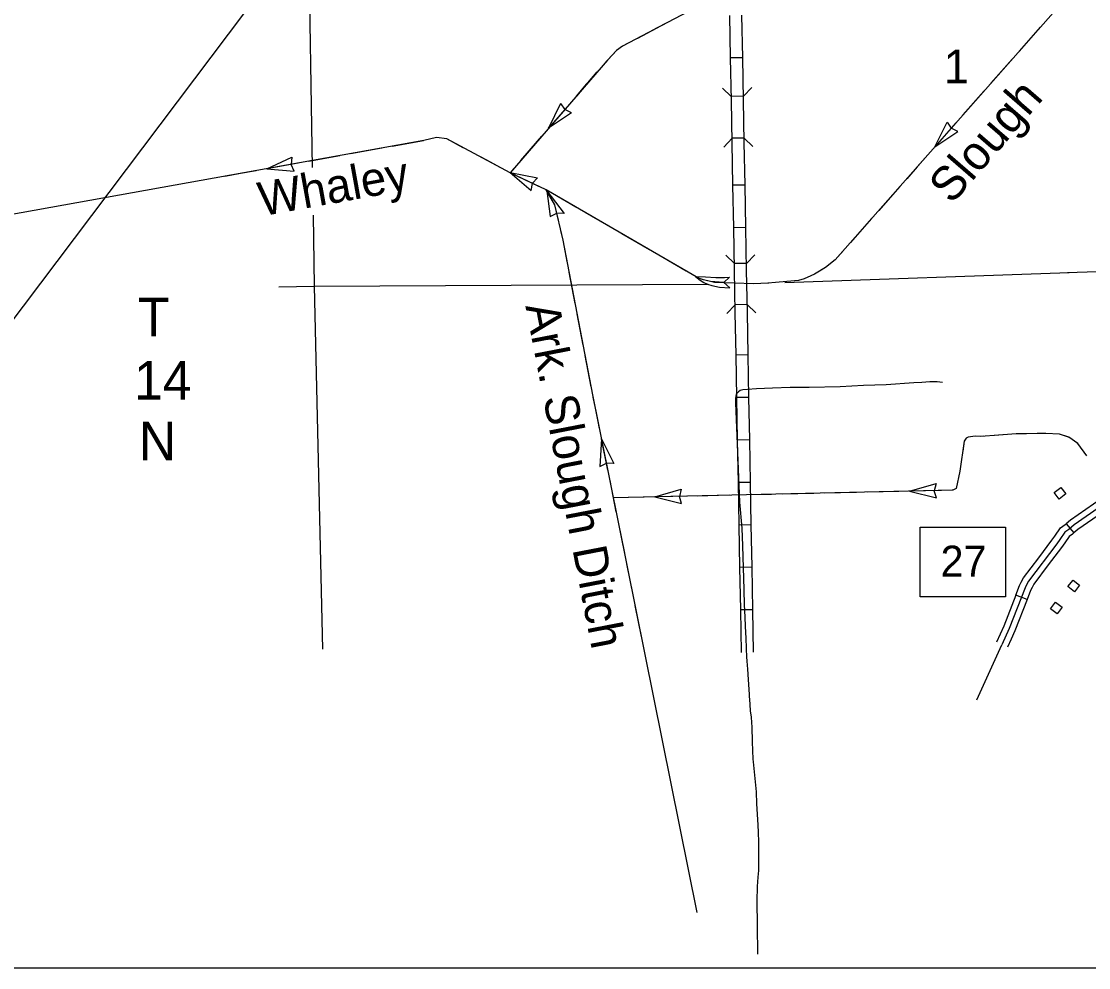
# Model space of a CAD drawing. Extents: x 1671357 to 13005564, y 567358 to 14261451.
# Drawn here: x 12758292.019 to 12758296.447, y 14259938.354 to 14259942.281 of the extents above; entities that cross this region are included whole.
import ezdxf

# ---------------------------------------------------------------- set-up
doc = ezdxf.new("R2010")
doc.units = 0
for name, color, linetype in [('31', 7, 'Continuous'), ('32', 7, 'Continuous'), ('35', 7, 'Continuous'), ('38', 7, 'Continuous'), ('43', 7, 'Continuous'), ('5', 7, 'Continuous'), ('56', 7, 'Continuous'), ('Default', 7, 'Continuous')]:
    doc.layers.add(name, color=color, linetype=linetype)

msp = doc.modelspace()

# ---------------------------------------------------------------- linework, layer by layer
at = {"layer": '31'}
for p, q in [((12758296.3532, 14259940.196), (12758296.3854, 14259940.1577)), ((12758296.2798, 14259940.025), (12758296.2798, 14259940.025)), ((12758296.1917, 14259939.8817), (12758296.1451, 14259939.9))]:
    msp.add_line(p, q, dxfattribs=at)
for points in [[(12758296.6997, 14259940.4082), (12758296.387, 14259940.1916), (12758296.3643, 14259940.1726), (12758296.3484, 14259940.1613), (12758296.3272, 14259940.1307), (12758296.3148, 14259940.1128), (12758296.1978, 14259939.9581), (12758296.1897, 14259939.9424), (12758296.1835, 14259939.9294), (12758296.1177, 14259939.7617), (12758296.0875, 14259939.6941)], [(12758296.4987, 14259940.2995), (12758296.3718, 14259940.2116), (12758296.3532, 14259940.196)], [(12758296.5272, 14259940.2583), (12758296.4022, 14259940.1717), (12758296.3854, 14259940.1577)], [(12758296.2398, 14259940.0552), (12758296.2945, 14259940.1274), (12758296.3066, 14259940.1449), (12758296.3303, 14259940.1792), (12758296.349, 14259940.1925), (12758296.3532, 14259940.196)], [(12758296.3854, 14259940.1577), (12758296.3796, 14259940.1528), (12758296.3665, 14259940.1434), (12758296.3478, 14259940.1164), (12758296.3351, 14259940.0981), (12758296.2798, 14259940.025)], [(12758296.1451, 14259939.9), (12758296.1605, 14259939.9394), (12758296.1672, 14259939.9535), (12758296.1765, 14259939.9715), (12758296.2398, 14259940.0552)], [(12758296.2798, 14259940.025), (12758296.219, 14259939.9447), (12758296.2121, 14259939.9313), (12758296.2065, 14259939.9194), (12758296.1917, 14259939.8817)], [(12758296.1451, 14259939.9), (12758296.0946, 14259939.7713), (12758296.0795, 14259939.7376)], [(12758296.1917, 14259939.8817), (12758296.1408, 14259939.752), (12758296.1253, 14259939.7172)], [(12758296.0795, 14259939.7376), (12758296.0647, 14259939.7044)], [(12758295.9837, 14259939.4646), (12758296.0875, 14259939.6941)], [(12758296.1253, 14259939.7172), (12758296.1104, 14259939.6839)]]:
    msp.add_lwpolyline(points, dxfattribs=at)
at = {"layer": '32'}
for p, q in [((12758295.0118, 14259942.1303), (12758294.9618, 14259942.1294)), ((12758295.0148, 14259941.9702), (12758294.9647, 14259941.9692)), ((12758295.018, 14259941.7967), (12758294.9679, 14259941.7958)), ((12758295.0215, 14259941.6016), (12758294.9715, 14259941.6007)), ((12758295.0248, 14259941.4253), (12758294.9747, 14259941.4244)), ((12758295.0275, 14259941.2767), (12758294.9774, 14259941.2758)), ((12758295.0306, 14259941.1059), (12758294.9806, 14259941.105)), ((12758295.0345, 14259940.8966), (12758294.9844, 14259940.8957)), ((12758295.0377, 14259940.7203), (12758294.9877, 14259940.7194)), ((12758295.041, 14259940.5441), (12758294.9909, 14259940.5432)), ((12758295.0442, 14259940.3678), (12758294.9942, 14259940.3669)), ((12758295.0475, 14259940.1916), (12758294.9974, 14259940.1907)), ((12758295.0507, 14259940.0153), (12758295.0006, 14259940.0144)), ((12758295.0539, 14259939.8391), (12758295.0039, 14259939.8382))]:
    msp.add_line(p, q, dxfattribs=at)
for points in [[(12758291.3155, 14259940.156), (12758292.9509, 14259942.3231)], [(12758294.9618, 14259942.1294), (12758294.9585, 14259942.3057)], [(12758295.0118, 14259942.1303), (12758295.0086, 14259942.3066)], [(12758294.965, 14259941.9532), (12758294.9618, 14259942.1294)], [(12758295.0151, 14259941.9541), (12758295.0118, 14259942.1303)], [(12758294.9682, 14259941.7769), (12758294.965, 14259941.9532)], [(12758295.0183, 14259941.7778), (12758295.0151, 14259941.9541)], [(12758294.9715, 14259941.6007), (12758294.9682, 14259941.7769)], [(12758295.0215, 14259941.6016), (12758295.0183, 14259941.7778)], [(12758294.9747, 14259941.4244), (12758294.9715, 14259941.6007)], [(12758295.0248, 14259941.4253), (12758295.0215, 14259941.6016)], [(12758294.978, 14259941.2482), (12758294.9747, 14259941.4244)], [(12758295.028, 14259941.2491), (12758295.0248, 14259941.4253)], [(12758294.9812, 14259941.0719), (12758294.978, 14259941.2482)], [(12758295.0313, 14259941.0728), (12758295.028, 14259941.2491)], [(12758294.9844, 14259940.8957), (12758294.9812, 14259941.0719)], [(12758295.0345, 14259940.8966), (12758295.0313, 14259941.0728)], [(12758294.9877, 14259940.7194), (12758294.9844, 14259940.8957)], [(12758295.0377, 14259940.7203), (12758295.0345, 14259940.8966)], [(12758294.9909, 14259940.5432), (12758294.9877, 14259940.7194)], [(12758295.041, 14259940.5441), (12758295.0377, 14259940.7203)], [(12758294.9942, 14259940.3669), (12758294.9909, 14259940.5432)], [(12758295.0442, 14259940.3678), (12758295.041, 14259940.5441)], [(12758294.9974, 14259940.1907), (12758294.9942, 14259940.3669)], [(12758295.0475, 14259940.1916), (12758295.0442, 14259940.3678)], [(12758295.0006, 14259940.0144), (12758294.9974, 14259940.1907)], [(12758295.0507, 14259940.0153), (12758295.0475, 14259940.1916)], [(12758295.0039, 14259939.8382), (12758295.0006, 14259940.0144)], [(12758295.0539, 14259939.8391), (12758295.0507, 14259940.0153)], [(12758295.0071, 14259939.6619), (12758295.0039, 14259939.8382)], [(12758295.0572, 14259939.6629), (12758295.0539, 14259939.8391)]]:
    msp.add_lwpolyline(points, dxfattribs=at)
at = {"layer": '35'}
for p, q in [((12758294.2565, 14259941.9407), (12758294.2737, 14259941.9155)), ((12758294.3014, 14259941.902), (12758294.274, 14259941.9153))]:
    msp.add_line(p, q, dxfattribs=at)
for points in [[(12758294.9447, 14259942.4071), (12758294.5128, 14259942.1776), (12758294.4877, 14259942.1599), (12758294.4502, 14259942.1202), (12758294.0477, 14259941.6529)], [(12758294.0629, 14259941.6705), (12758294.0477, 14259941.6529)]]:
    msp.add_lwpolyline(points, dxfattribs=at)
at = {"layer": '38'}
for p, q in [((12758294.9896, 14259941.9698), (12758294.9896, 14259941.9698)), ((12758294.9928, 14259941.7961), (12758294.9928, 14259941.7961)), ((12758295.0053, 14259941.105), (12758295.0053, 14259941.105))]:
    msp.add_line(p, q, dxfattribs=at)
for points in [[(12758294.9285, 14259942.0041), (12758294.9646, 14259941.9693)], [(12758295.0148, 14259941.9702), (12758295.0495, 14259942.0063)], [(12758294.9679, 14259941.7957), (12758294.9331, 14259941.7597)], [(12758295.0539, 14259941.762), (12758295.0179, 14259941.7967)], [(12758294.9775, 14259941.2758), (12758294.9417, 14259941.3108)], [(12758295.0625, 14259941.3126), (12758295.0275, 14259941.2768)], [(12758294.9807, 14259941.1049), (12758294.9459, 14259941.0688)], [(12758295.0668, 14259941.071), (12758295.0307, 14259941.1058)]]:
    msp.add_lwpolyline(points, dxfattribs=at)
at = {"layer": '43'}
for p, q in [((12758294.2565, 14259941.9407), (12758294.2067, 14259941.8375)), ((12758294.3014, 14259941.902), (12758294.2067, 14259941.8375)), ((12758295.8089, 14259941.7606), (12758295.8598, 14259941.8632)), ((12758295.8598, 14259941.8632), (12758295.8767, 14259941.8378)), ((12758295.8089, 14259941.7606), (12758295.9043, 14259941.824)), ((12758295.9043, 14259941.824), (12758295.877, 14259941.8376)), ((12758293.037, 14259941.669), (12758293.1407, 14259941.7177)), ((12758293.1407, 14259941.7177), (12758293.1381, 14259941.6873)), ((12758293.037, 14259941.669), (12758293.1512, 14259941.6593)), ((12758293.1512, 14259941.6593), (12758293.1382, 14259941.6869)), ((12758294.0471, 14259941.6532), (12758294.1343, 14259941.5788)), ((12758294.0471, 14259941.6532), (12758294.1598, 14259941.6324)), ((12758294.1598, 14259941.6324), (12758294.14, 14259941.6092)), ((12758294.1343, 14259941.5788), (12758294.1398, 14259941.6088)), ((12758294.199, 14259941.578), (12758294.2134, 14259941.4706)), ((12758294.199, 14259941.578), (12758294.2711, 14259941.484)), ((12758294.2134, 14259941.4706), (12758294.2403, 14259941.4849)), ((12758294.2711, 14259941.484), (12758294.2407, 14259941.485)), ((12758294.9566, 14259941.2201), (12758294.9336, 14259941.1972)), ((12758294.9578, 14259941.1748), (12758294.9336, 14259941.1972)), ((12758294.4265, 14259940.5485), (12758294.4193, 14259940.4341)), ((12758294.4265, 14259940.5485), (12758294.4775, 14259940.4458)), ((12758294.4193, 14259940.4341), (12758294.4466, 14259940.4477)), ((12758294.4775, 14259940.4458), (12758294.447, 14259940.4477)), ((12758294.6467, 14259940.3071), (12758294.7566, 14259940.3392)), ((12758294.7566, 14259940.3392), (12758294.7494, 14259940.3096)), ((12758295.7041, 14259940.3308), (12758295.8141, 14259940.363)), ((12758295.8141, 14259940.363), (12758295.8068, 14259940.3333)), ((12758294.6467, 14259940.3071), (12758294.758, 14259940.2799)), ((12758294.758, 14259940.2799), (12758294.7494, 14259940.3092)), ((12758295.7041, 14259940.3308), (12758295.8154, 14259940.3037)), ((12758295.8154, 14259940.3037), (12758295.8068, 14259940.3329))]:
    msp.add_line(p, q, dxfattribs=at)
for points in [[(12758296.435, 14259942.4717), (12758295.3961, 14259941.2916), (12758295.3552, 14259941.2598), (12758295.3095, 14259941.2316), (12758295.2671, 14259941.2128), (12758295.2433, 14259941.2062), (12758295.1162, 14259941.1942), (12758295.0582, 14259941.1913), (12758294.895, 14259941.198), (12758294.8485, 14259941.209), (12758294.8278, 14259941.2155), (12758294.1967, 14259941.582), (12758294.0477, 14259941.6529), (12758293.7846, 14259941.7931), (12758293.7419, 14259941.7995), (12758293.689, 14259941.786), (12758291.7325, 14259941.4348), (12758291.6882, 14259941.4307), (12758291.6611, 14259941.4324), (12758291.6542, 14259941.4341)], [(12758294.6917, 14259942.2727), (12758294.575, 14259942.2107)], [(12758294.6917, 14259942.2727), (12758294.6334, 14259942.2417)], [(12758296.2457, 14259942.2567), (12758296.1584, 14259942.1575)], [(12758294.5944, 14259942.221), (12758294.575, 14259942.2107)], [(12758294.5361, 14259942.19), (12758294.5128, 14259942.1776), (12758294.4877, 14259942.1599), (12758294.4733, 14259942.1439), (12758294.4502, 14259942.1202), (12758294.4368, 14259942.1047)], [(12758294.5361, 14259942.19), (12758294.5128, 14259942.1776), (12758294.4877, 14259942.1599), (12758294.4817, 14259942.1532)], [(12758294.4512, 14259942.1213), (12758294.4502, 14259942.1202), (12758294.4368, 14259942.1047)], [(12758296.1293, 14259942.1244), (12758296.0419, 14259942.0252)], [(12758294.3218, 14259941.9711), (12758294.408, 14259942.0713)], [(12758294.3937, 14259942.0546), (12758294.408, 14259942.0713)], [(12758294.3649, 14259942.0212), (12758294.3218, 14259941.9711)], [(12758294.3218, 14259941.9711), (12758294.3649, 14259942.0212)], [(12758294.3218, 14259941.9711), (12758294.3649, 14259942.0212)], [(12758296.0128, 14259941.9921), (12758295.9254, 14259941.8929)], [(12758294.2565, 14259941.9407), (12758294.2067, 14259941.8375)], [(12758294.293, 14259941.9377), (12758294.2067, 14259941.8375)], [(12758294.293, 14259941.9377), (12758294.2211, 14259941.8542)], [(12758294.3014, 14259941.902), (12758294.2104, 14259941.84)], [(12758294.2211, 14259941.8542), (12758294.2067, 14259941.8375)], [(12758294.2211, 14259941.8542), (12758294.2067, 14259941.8375)], [(12758295.8963, 14259941.8598), (12758295.8089, 14259941.7606)], [(12758294.1348, 14259941.754), (12758294.178, 14259941.8041)], [(12758294.1348, 14259941.754), (12758294.178, 14259941.8041)], [(12758294.1348, 14259941.754), (12758294.178, 14259941.8041)], [(12758294.2067, 14259941.8375), (12758294.2086, 14259941.8415)], [(12758294.2067, 14259941.8375), (12758294.2086, 14259941.8415)], [(12758294.2067, 14259941.8375), (12758294.2104, 14259941.84)], [(12758294.2067, 14259941.8375), (12758294.2104, 14259941.84)], [(12758293.6876, 14259941.7858), (12758293.5575, 14259941.7624)], [(12758293.8527, 14259941.7568), (12758293.7846, 14259941.7931), (12758293.7419, 14259941.7995), (12758293.7304, 14259941.7965)], [(12758293.3406, 14259941.7235), (12758293.2105, 14259941.7001)], [(12758293.5141, 14259941.7546), (12758293.384, 14259941.7313)], [(12758293.9499, 14259941.705), (12758293.8916, 14259941.7361)], [(12758294.1348, 14259941.754), (12758294.0917, 14259941.7039)], [(12758294.0917, 14259941.7039), (12758294.1348, 14259941.754)], [(12758294.0917, 14259941.7039), (12758294.1348, 14259941.754)], [(12758295.7798, 14259941.7275), (12758295.7361, 14259941.6779)], [(12758293.1671, 14259941.6923), (12758293.037, 14259941.669)], [(12758294.0083, 14259941.6739), (12758293.9499, 14259941.705)], [(12758295.7361, 14259941.6779), (12758295.6924, 14259941.6282)], [(12758292.9285, 14259941.6495), (12758292.8635, 14259941.6378)], [(12758292.9936, 14259941.6612), (12758292.9285, 14259941.6495)], [(12758294.1665, 14259941.5964), (12758294.0477, 14259941.6529), (12758294.0471, 14259941.6532)], [(12758294.8232, 14259938.5829), (12758294.3896, 14259940.7311), (12758294.2664, 14259941.3729), (12758294.2325, 14259941.5194), (12758294.1967, 14259941.582)], [(12758295.6633, 14259941.5952), (12758295.576, 14259941.4959)], [(12758294.2471, 14259941.4563), (12758294.2325, 14259941.5194), (12758294.199, 14259941.578)], [(12758294.3202, 14259941.5103), (12758294.2059, 14259941.5766)], [(12758294.4727, 14259941.4217), (12758294.3583, 14259941.4881)], [(12758295.5468, 14259941.4629), (12758295.4595, 14259941.3636)], [(12758294.2835, 14259941.2839), (12758294.2664, 14259941.3729), (12758294.2571, 14259941.4134)], [(12758294.6251, 14259941.3332), (12758294.5108, 14259941.3996)], [(12758295.4304, 14259941.3305), (12758295.3961, 14259941.2916), (12758295.3552, 14259941.2598), (12758295.3309, 14259941.2448)], [(12758294.7776, 14259941.2447), (12758294.6632, 14259941.3111)], [(12758294.3168, 14259941.1108), (12758294.2918, 14259941.2406)], [(12758294.878, 14259941.202), (12758294.8485, 14259941.209), (12758294.8278, 14259941.2155), (12758294.8157, 14259941.2226)], [(12758294.8157, 14259941.2226), (12758294.8578, 14259941.2212), (12758294.9008, 14259941.2187), (12758294.9358, 14259941.2175), (12758294.9566, 14259941.2201)], [(12758294.8157, 14259941.2226), (12758294.8351, 14259941.2076), (12758294.8503, 14259941.1979), (12758294.8651, 14259941.191), (12758294.8836, 14259941.1842), (12758294.9149, 14259941.178), (12758294.9578, 14259941.1748)], [(12758294.9336, 14259941.1972), (12758294.8956, 14259941.1998), (12758294.878, 14259941.202)], [(12758295.1197, 14259941.1946), (12758295.1162, 14259941.1942), (12758295.0582, 14259941.1913), (12758295.0291, 14259941.1925)], [(12758295.2922, 14259941.2239), (12758295.2671, 14259941.2128), (12758295.2433, 14259941.2062), (12758295.1636, 14259941.1987)], [(12758294.35, 14259940.9376), (12758294.3251, 14259941.0675)], [(12758294.3832, 14259940.7645), (12758294.3583, 14259940.8944)], [(12758294.4047, 14259940.6565), (12758294.3916, 14259940.7213)], [(12758294.4178, 14259940.5917), (12758294.4047, 14259940.6565)], [(12758296.4389, 14259940.4781), (12758296.4019, 14259940.5286), (12758296.3648, 14259940.555), (12758296.3266, 14259940.5682), (12758296.2701, 14259940.5707), (12758296.1466, 14259940.5686), (12758296.0003, 14259940.5582), (12758295.9766, 14259940.559), (12758295.9477, 14259940.5558), (12758295.9395, 14259940.5518), (12758295.9309, 14259940.5394), (12758295.9123, 14259940.4144), (12758295.8976, 14259940.3428), (12758295.8839, 14259940.3349), (12758294.4767, 14259940.3032)], [(12758296.1888, 14259940.5693), (12758296.1466, 14259940.5686), (12758296.0568, 14259940.5622)], [(12758296.3629, 14259940.5557), (12758296.3266, 14259940.5682), (12758296.2701, 14259940.5707), (12758296.2328, 14259940.5701)], [(12758294.4527, 14259940.4189), (12758294.4265, 14259940.5485)], [(12758296.0128, 14259940.5591), (12758296.0003, 14259940.5582), (12758295.9766, 14259940.559), (12758295.9477, 14259940.5558), (12758295.9395, 14259940.5518), (12758295.9309, 14259940.5394), (12758295.9246, 14259940.4972)], [(12758296.4389, 14259940.4781), (12758296.4019, 14259940.5286), (12758296.399, 14259940.5306)], [(12758295.9181, 14259940.4536), (12758295.9123, 14259940.4144), (12758295.8976, 14259940.3428), (12758295.8839, 14259940.3349), (12758295.8803, 14259940.3348)], [(12758294.4875, 14259940.2461), (12758294.4614, 14259940.3757)], [(12758294.5365, 14259940.3046), (12758294.4767, 14259940.3032)], [(12758294.6026, 14259940.3061), (12758294.5365, 14259940.3046)], [(12758294.7788, 14259940.31), (12758294.6467, 14259940.3071)], [(12758294.9551, 14259940.314), (12758294.8229, 14259940.311)], [(12758295.1313, 14259940.318), (12758295.0452, 14259940.316)], [(12758295.3075, 14259940.3219), (12758295.1754, 14259940.3189)], [(12758295.4838, 14259940.3259), (12758295.3516, 14259940.3229)], [(12758295.5939, 14259940.3284), (12758295.5278, 14259940.3269)], [(12758295.66, 14259940.3298), (12758295.5939, 14259940.3284)], [(12758295.8362, 14259940.3338), (12758295.7041, 14259940.3308)], [(12758294.5224, 14259940.0733), (12758294.4963, 14259940.2029)], [(12758294.5573, 14259939.9005), (12758294.5311, 14259940.0301)], [(12758294.5922, 14259939.7277), (12758294.566, 14259939.8573)]]:
    msp.add_lwpolyline(points, dxfattribs=at)
at = {"layer": '5'}
for points in [[(12758293.2099, 14259942.6165), (12758293.226, 14259941.6744)], [(12758293.2294, 14259941.4764), (12758293.2344, 14259941.1823), (12758293.2688, 14259939.675)], [(12758295.187, 14259941.1978), (12758296.3659, 14259941.2391)], [(12758296.3598, 14259941.2389), (12758296.7648, 14259941.253), (12758297.1586, 14259941.265)], [(12758296.3598, 14259941.2389), (12758296.3659, 14259941.2391)], [(12758293.0869, 14259941.1794), (12758293.2344, 14259941.1823), (12758294.8683, 14259941.1908)]]:
    msp.add_lwpolyline(points, dxfattribs=at)
at = {"layer": '56'}
for points in [[(12758296.3252, 14259940.298), (12758296.3036, 14259940.3253), (12758296.331, 14259940.3469), (12758296.3525, 14259940.3196)], [(12758296.3608, 14259939.9354), (12758296.3826, 14259939.9625), (12758296.4098, 14259939.9407), (12758296.388, 14259939.9136)], [(12758296.3164, 14259939.822), (12758296.2885, 14259939.8428), (12758296.3094, 14259939.8707), (12758296.3372, 14259939.8499)]]:
    msp.add_lwpolyline(points, close=True, dxfattribs=at)
at = {"layer": 'Default'}
msp.add_line((12758284.583, 14259938.3536), (12758318.61, 14259938.3536), dxfattribs=at)
msp.add_lwpolyline([(12758295.8401, 14259940.7821), (12758295.8185, 14259940.7848), (12758295.7875, 14259940.7844), (12758295.7553, 14259940.7827), (12758295.7223, 14259940.7806), (12758295.6077, 14259940.7731), (12758295.5132, 14259940.7693), (12758295.4162, 14259940.7647), (12758295.2875, 14259940.7622), (12758295.2093, 14259940.7609), (12758295.1348, 14259940.7588), (12758295.0692, 14259940.7559), (12758295.0324, 14259940.7538), (12758295.0119, 14259940.7513), (12758295.0019, 14259940.7488), (12758294.9939, 14259940.7442), (12758294.9852, 14259940.7337), (12758294.9814, 14259940.7153), (12758294.9814, 14259940.6973), (12758294.9985, 14259940.285), (12758295.0076, 14259940.1776), (12758295.0103, 14259940.1049), (12758295.0164, 14259939.9235), (12758295.0184, 14259939.8587), (12758295.0195, 14259939.8371), (12758295.0239, 14259939.7413), (12758295.0245, 14259939.7235), (12758295.0268, 14259939.6772), (12758295.0282, 14259939.6431), (12758295.0295, 14259939.6251), (12758295.0314, 14259939.5926), (12758295.0345, 14259939.5503), (12758295.0382, 14259939.4875), (12758295.0386, 14259939.4795), (12758295.0395, 14259939.4661), (12758295.0411, 14259939.4461), (12758295.0427, 14259939.4195), (12758295.0443, 14259939.4097), (12758295.0464, 14259939.3945), (12758295.0486, 14259939.3692), (12758295.0491, 14259939.3531), (12758295.0516, 14259939.291), (12758295.0545, 14259939.2194), (12758295.055, 14259939.2078), (12758295.0584, 14259939.1802), (12758295.0675, 14259939.0834), (12758295.0695, 14259939.034), (12758295.0745, 14259938.9458), (12758295.0766, 14259938.9144), (12758295.0768, 14259938.8757), (12758295.0773, 14259938.8126), (12758295.0767, 14259938.7565), (12758295.075, 14259938.7296), (12758295.072, 14259938.6907), (12758295.0708, 14259938.6292), (12758295.0714, 14259938.5293), (12758295.0738, 14259938.4097)], dxfattribs=at)
msp.add_lwpolyline([(12758295.7475, 14259940.182), (12758296.1022, 14259940.182), (12758296.1022, 14259939.893), (12758295.7475, 14259939.893)], close=True, dxfattribs=at)

# ---------------------------------------------------------------- texts
at = {"layer": '43'}
for s, height, rotation, p in [('Slough', 0.14102, 49.114, (12758295.8792, 14259941.5181)), ('Whaley', 0.14102, 10.2568, (12758293.0161, 14259941.4718)), ('Ark. Slough Ditch', 0.141023, 280.9422, (12758294.11, 14259941.0999))]:
    msp.add_text(s, height=height, rotation=rotation, dxfattribs=at).set_placement(p)
at = {"layer": '5'}
msp.add_text('1', height=0.141, dxfattribs=at).set_placement((12758295.846, 14259942.0233))
at = {"layer": 'Default'}
for s, height, p in [('T', 0.16, (12758292.5029, 14259940.9745)), ('14', 0.16, (12758292.4866, 14259940.7115)), ('N', 0.16, (12758292.5067, 14259940.4593)), ('27', 0.12825, (12758295.8327, 14259939.9769))]:
    msp.add_text(s, height=height, dxfattribs=at).set_placement(p)

doc.saveas('drawing.dxf')
